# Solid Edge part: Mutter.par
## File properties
Sűrűség: 0,000 kg/m^3
Pontosság: 0,990
Author: ahadarics
Last saved by: psaghy
Revision: 77
Username: ahadarics
Dokumentum tartalom típus: 0
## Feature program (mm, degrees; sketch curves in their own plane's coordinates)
base feature "unnamed BaseFeature 1"
sketch for "Furat_1" plane through (0, 0, 0) normal (-1, 0, 0) x-axis (0, -1, 0)
  hole centre (0, 0) bore radius 22.9175
hole "Furat_1" through  StartChamferOffset = 1.5 mm; StartChamferAngle = 45 deg
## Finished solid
Body 1: solid body, 19 faces, 49 edges, 32 vertices.
  Faces by surface: plane 8, cylinder 7, cone 4
  Edges by curve: circle 22, line 15, spline 12
Bounding box of the edges (mm): 18.000 x 86.250 x 75.000, from (0, -43.125, -37.5) to (18, 43.125, 37.5).
Cylindrical faces by radius (mm): R22.9175 x1, R43.125 x6
Conical faces (half-angle, radius in mm at the cone's reference point): 45 deg R24.415 x1, 45 deg R24.4175 x1, 75 deg R40.0625 x2
Planar faces by outward normal: +x 1, +z 1, -x 1, -z 1, oblique 4
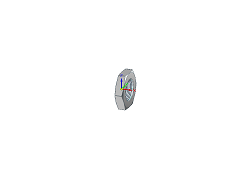
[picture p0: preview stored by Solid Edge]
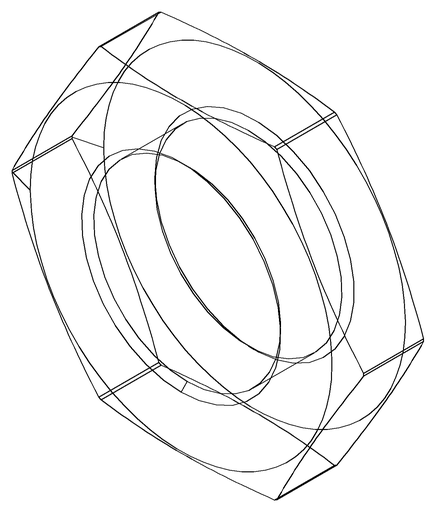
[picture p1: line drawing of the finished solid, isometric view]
